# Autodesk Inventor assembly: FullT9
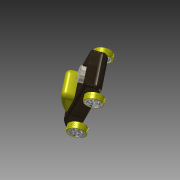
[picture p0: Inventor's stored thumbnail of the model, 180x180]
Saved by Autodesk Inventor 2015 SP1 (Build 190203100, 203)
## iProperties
Created: 2016-01
Part Number: FullT9
Document SubType Name: Assembly
Designer: S190015
Author: S190015
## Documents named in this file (5)
- P:\IED\AssemblyAutoMoblox\FullT9.iam
- P:\IED\AssemblyAutoMoblox\BackAssembly.iam
- P:\IED\AssemblyAutoMoblox\MiddleAssembly.iam
- P:\IED\AssemblyAutoMoblox\FrontAssembly.iam
- P:\IED\7.7\assemblyEnhancement.iam
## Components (4 placed, 4 different names)
1. BackAssembly:1 [sub-assembly] — Mate:2, Flush:3, Flush:4, Mate:3, Mate:4
2. MiddleAssembly:1 [sub-assembly] — Mate:1, Flush:1, Flush:2, Mate:2, Flush:3, Flush:4
3. FrontAssembly:1 [sub-assembly] — Mate:1, Flush:1, Flush:2
4. assemblyEnhancement:1 [sub-assembly] — Mate:3, Mate:4
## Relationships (8: Mate 4, Flush 4)
- Mate:1: MiddleAssembly:1 ↔ FrontAssembly:1
- Flush:1: MiddleAssembly:1 ↔ FrontAssembly:1
- Flush:2: MiddleAssembly:1 ↔ FrontAssembly:1
- Mate:2: BackAssembly:1 ↔ MiddleAssembly:1
- Flush:3: BackAssembly:1 ↔ MiddleAssembly:1
- Flush:4: BackAssembly:1 ↔ MiddleAssembly:1
- Mate:3: BackAssembly:1 ↔ assemblyEnhancement:1
- Mate:4: BackAssembly:1 ↔ assemblyEnhancement:1
